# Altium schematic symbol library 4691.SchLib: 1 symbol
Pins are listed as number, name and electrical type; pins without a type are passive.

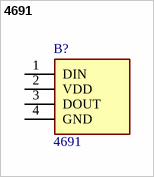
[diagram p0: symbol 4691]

## 4691
designator B?
Adafruit Accessories NeoPixel Side-Light RGB LED w/ Integrated Driver Chip - 10-pack - SK6812B 4020; Geometry.Height: 2.1mm
footprint 4691
pins: 1 DIN, 2 VDD, 3 DOUT, 4 GND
